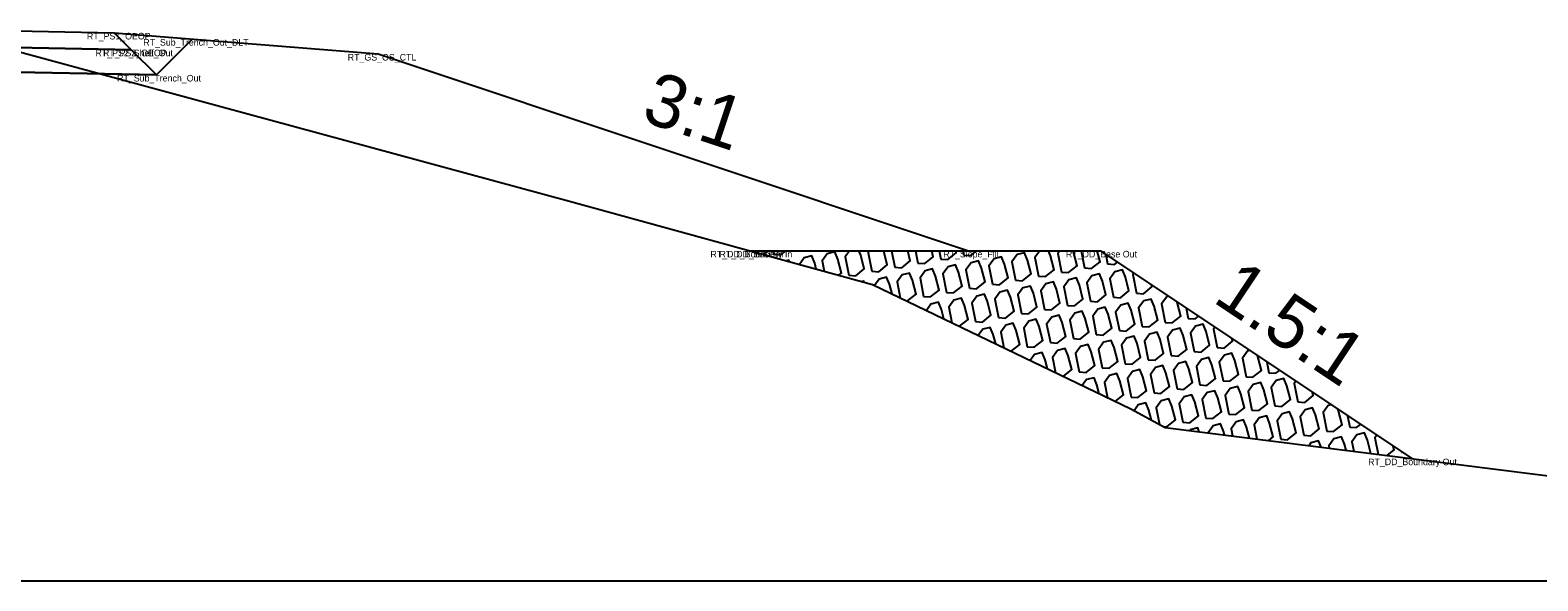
# Model space of a CAD drawing. Extents: x -26 to 203, y -10 to 20020.
# Drawn here: x 111.72 to 134.58, y 18500 to 18508.34 of the extents above; entities that cross this region are included whole.
import ezdxf

# ---------------------------------------------------------------- set-up
doc = ezdxf.new("R2010")
doc.units = 0
for name, color, linetype in [('Default', 7, 'Continuous'), ('Exist Cross Section Cell', 7, 'Continuous'), ('Exist XS Ground Line', 7, 'Continuous'), ('Old_Level_1', 7, 'Continuous'), ('Prop CMT Pvmt Surface Shoulder', 7, 'Continuous'), ('Prop CMT Rip Rap Class II', 7, 'Continuous'), ('Prop CMT Shld Paved Course 1', 7, 'Continuous'), ('Prop CMT Shld Paved Course 2', 7, 'Continuous'), ('Prop CMT Slope Grass', 7, 'Continuous'), ('Prop CMT Subgrade Earthwork', 7, 'Continuous'), ('Prop XS Side Slope Text', 7, 'Continuous')]:
    doc.layers.add(name, color=color, linetype=linetype)

msp = doc.modelspace()

# ---------------------------------------------------------------- linework, layer by layer
at = {"layer": 'Exist Cross Section Cell'}
msp.add_line((100, 18500), (200, 18500), dxfattribs=at)
at = {"layer": 'Exist XS Ground Line'}
for p, q in [((111.141, 18508.127), (119.901, 18505.754)), ((119.901, 18505.754), (124.498, 18504.488)), ((124.498, 18504.488), (128.412, 18502.604)), ((128.412, 18502.604), (128.933, 18502.324)), ((128.933, 18502.324), (135.814, 18501.456))]:
    msp.add_line(p, q, dxfattribs=at)
at = {"layer": 'Old_Level_1'}
for p, q in [((122.993, 18505), (123.003, 18504.949)), ((124.786, 18505), (124.835, 18504.752)), ((125.146, 18505), (125.183, 18504.813)), ((125.507, 18505), (125.532, 18504.875)), ((125.868, 18505), (125.881, 18504.936)), ((126.229, 18505), (126.229, 18504.998)), ((127.661, 18505), (127.712, 18504.74)), ((128.032, 18504.946), (128.061, 18504.801)), ((129.254, 18504.132), (129.285, 18503.977)), ((130.476, 18503.317), (130.508, 18503.154)), ((131.697, 18502.502), (131.732, 18502.33)), ((132.516, 18501.957), (132.518, 18501.949)), ((132.518, 18501.949), (132.529, 18501.948))]:
    msp.add_line(p, q, dxfattribs=at)
for points in [[(122.841, 18504.944), (122.889, 18504.983), (122.885, 18505)], [(123.003, 18504.949), (123.108, 18504.941), (123.182, 18505)], [(123.982, 18504.63), (124.024, 18504.663), (123.969, 18504.874), (123.924, 18504.983), (123.81, 18504.954), (123.733, 18504.848), (123.765, 18504.69)], [(124.148, 18505), (124.082, 18504.909), (124.138, 18504.629)], [(124.138, 18504.629), (124.243, 18504.621), (124.372, 18504.725), (124.318, 18504.935), (124.291, 18505)], [(124.452, 18505), (124.431, 18504.971), (124.486, 18504.691)], [(124.486, 18504.691), (124.591, 18504.683), (124.721, 18504.786), (124.667, 18504.997), (124.665, 18505)], [(124.835, 18504.752), (124.94, 18504.744), (125.07, 18504.848), (125.03, 18505)], [(125.183, 18504.813), (125.289, 18504.806), (125.418, 18504.909), (125.395, 18505)], [(125.532, 18504.875), (125.637, 18504.867), (125.767, 18504.971), (125.759, 18505)], [(125.881, 18504.936), (125.986, 18504.929), (126.075, 18505)], [(126.229, 18504.998), (126.334, 18504.99), (126.347, 18505)], [(127.034, 18505), (126.96, 18504.897), (127.015, 18504.617)], [(127.015, 18504.617), (127.12, 18504.609), (127.25, 18504.712), (127.196, 18504.923), (127.164, 18505)], [(127.338, 18505), (127.308, 18504.958), (127.364, 18504.678)], [(127.364, 18504.678), (127.469, 18504.671), (127.599, 18504.774), (127.544, 18504.984), (127.538, 18505)], [(127.712, 18504.74), (127.818, 18504.732), (127.947, 18504.835), (127.905, 18505)], [(123.237, 18504.835), (123.227, 18504.861), (123.185, 18504.85)], [(123.644, 18504.723), (123.621, 18504.812), (123.576, 18504.922), (123.462, 18504.893), (123.39, 18504.793)], [(126.318, 18504.494), (126.423, 18504.486), (126.553, 18504.589), (126.498, 18504.8), (126.453, 18504.91), (126.339, 18504.88), (126.262, 18504.774), (126.318, 18504.494)], [(128.061, 18504.801), (128.166, 18504.794), (128.209, 18504.828)], [(124.369, 18504.523), (124.362, 18504.541), (124.333, 18504.533)], [(124.793, 18504.346), (124.755, 18504.493), (124.71, 18504.602), (124.597, 18504.573), (124.525, 18504.475)], [(125.01, 18504.242), (125.029, 18504.24), (125.158, 18504.344), (125.104, 18504.554), (125.059, 18504.664), (124.945, 18504.634), (124.868, 18504.528), (124.916, 18504.287)], [(128.459, 18504.661), (128.443, 18504.639), (128.498, 18504.359)], [(125.803, 18503.86), (125.815, 18503.859), (125.945, 18503.962), (125.89, 18504.173), (125.845, 18504.283), (125.731, 18504.253), (125.654, 18504.147), (125.701, 18503.909)], [(126.058, 18503.928), (126.164, 18503.921), (126.293, 18504.024), (126.239, 18504.234), (126.194, 18504.344), (126.08, 18504.315), (126.003, 18504.208), (126.058, 18503.928)], [(126.756, 18504.051), (126.861, 18504.044), (126.99, 18504.147), (126.936, 18504.357), (126.891, 18504.467), (126.777, 18504.438), (126.7, 18504.331), (126.756, 18504.051)], [(128.498, 18504.359), (128.604, 18504.351), (128.733, 18504.454), (128.726, 18504.484)], [(128.986, 18504.31), (128.957, 18504.302), (128.88, 18504.196), (128.936, 18503.916)], [(125.579, 18503.968), (125.541, 18504.111), (125.496, 18504.221), (125.383, 18504.192), (125.313, 18504.096)], [(128.936, 18503.916), (129.041, 18503.908), (129.171, 18504.012), (129.116, 18504.222), (129.116, 18504.224)], [(126.364, 18503.59), (126.328, 18503.73), (126.282, 18503.84), (126.169, 18503.811), (126.101, 18503.717)], [(126.596, 18503.478), (126.601, 18503.478), (126.731, 18503.581), (126.676, 18503.792), (126.631, 18503.902), (126.517, 18503.872), (126.44, 18503.766), (126.487, 18503.531)], [(126.844, 18503.547), (126.95, 18503.54), (127.079, 18503.643), (127.025, 18503.853), (126.98, 18503.963), (126.866, 18503.934), (126.789, 18503.827), (126.844, 18503.547)], [(127.193, 18503.609), (127.298, 18503.601), (127.428, 18503.704), (127.373, 18503.915), (127.328, 18504.024), (127.214, 18503.995), (127.137, 18503.889), (127.193, 18503.609)], [(129.285, 18503.977), (129.39, 18503.97), (129.438, 18504.009)], [(129.687, 18503.843), (129.666, 18503.815), (129.722, 18503.535)], [(127.979, 18503.227), (128.084, 18503.22), (128.214, 18503.323), (128.159, 18503.534), (128.114, 18503.643), (128.001, 18503.614), (127.923, 18503.507), (127.979, 18503.227)], [(128.328, 18503.289), (128.433, 18503.281), (128.562, 18503.385), (128.508, 18503.595), (128.463, 18503.705), (128.349, 18503.675), (128.272, 18503.569), (128.328, 18503.289)], [(129.722, 18503.535), (129.827, 18503.527), (129.957, 18503.63), (129.947, 18503.67)], [(127.149, 18503.212), (127.114, 18503.349), (127.068, 18503.459), (126.955, 18503.43), (126.888, 18503.338)], [(127.388, 18503.097), (127.517, 18503.2), (127.462, 18503.411), (127.417, 18503.52), (127.303, 18503.491), (127.226, 18503.385), (127.272, 18503.153)], [(127.63, 18503.166), (127.736, 18503.158), (127.865, 18503.262), (127.811, 18503.472), (127.766, 18503.582), (127.652, 18503.552), (127.575, 18503.446), (127.63, 18503.166)], [(129.462, 18502.969), (129.568, 18502.962), (129.697, 18503.065), (129.643, 18503.275), (129.598, 18503.385), (129.484, 18503.356), (129.407, 18503.249), (129.462, 18502.969)], [(130.219, 18503.488), (130.181, 18503.479), (130.104, 18503.372), (130.16, 18503.092)], [(130.16, 18503.092), (130.265, 18503.085), (130.394, 18503.188), (130.34, 18503.398), (130.335, 18503.411)], [(128.176, 18502.718), (128.303, 18502.819), (128.248, 18503.03), (128.203, 18503.139), (128.089, 18503.11), (128.012, 18503.003), (128.058, 18502.775)], [(129.114, 18502.908), (129.219, 18502.9), (129.349, 18503.003), (129.294, 18503.214), (129.249, 18503.324), (129.135, 18503.294), (129.058, 18503.188), (129.114, 18502.908)], [(130.508, 18503.154), (130.613, 18503.146), (130.667, 18503.189)], [(127.934, 18502.834), (127.9, 18502.968), (127.855, 18503.078), (127.741, 18503.048), (127.676, 18502.959)], [(130.248, 18502.588), (130.354, 18502.581), (130.483, 18502.684), (130.429, 18502.894), (130.384, 18503.004), (130.27, 18502.975), (130.193, 18502.868), (130.248, 18502.588)], [(130.597, 18502.65), (130.702, 18502.642), (130.832, 18502.745), (130.777, 18502.956), (130.732, 18503.065), (130.618, 18503.036), (130.541, 18502.93), (130.597, 18502.65)], [(130.914, 18503.025), (130.89, 18502.991), (130.946, 18502.711)], [(128.725, 18502.436), (128.686, 18502.587), (128.641, 18502.697), (128.527, 18502.667), (128.462, 18502.578)], [(128.907, 18502.338), (128.959, 18502.335), (129.089, 18502.438), (129.034, 18502.648), (128.989, 18502.758), (128.875, 18502.729), (128.798, 18502.622), (128.849, 18502.37)], [(130.946, 18502.711), (131.051, 18502.703), (131.18, 18502.807), (131.168, 18502.856)], [(130.505, 18502.126), (130.572, 18502.18), (130.518, 18502.39), (130.473, 18502.5), (130.359, 18502.471), (130.282, 18502.364), (130.324, 18502.149)], [(131.451, 18502.667), (131.405, 18502.655), (131.327, 18502.548), (131.383, 18502.268)], [(131.383, 18502.268), (131.488, 18502.261), (131.618, 18502.364), (131.563, 18502.575), (131.554, 18502.598)], [(129.45, 18502.259), (129.427, 18502.316), (129.313, 18502.286), (129.307, 18502.277)], [(129.835, 18502.211), (129.82, 18502.267), (129.775, 18502.377), (129.662, 18502.348), (129.585, 18502.242)], [(130.212, 18502.163), (130.169, 18502.329), (130.124, 18502.438), (130.01, 18502.409), (129.933, 18502.303), (129.954, 18502.195)], [(131.732, 18502.33), (131.837, 18502.322), (131.896, 18502.37)], [(132.053, 18501.931), (132.001, 18502.132), (131.956, 18502.242), (131.842, 18502.212), (131.765, 18502.106), (131.793, 18501.963)], [(131.297, 18502.026), (131.259, 18502.119), (131.145, 18502.089), (131.116, 18502.049)], [(131.676, 18501.978), (131.652, 18502.071), (131.607, 18502.18), (131.493, 18502.151), (131.416, 18502.044), (131.423, 18502.01)], [(132.142, 18502.206), (132.114, 18502.167), (132.163, 18501.917)], [(132.299, 18501.9), (132.404, 18501.983), (132.389, 18502.042)]]:
    msp.add_lwpolyline(points, dxfattribs=at)
for points in [[(126.667, 18504.555), (126.772, 18504.548), (126.901, 18504.651), (126.847, 18504.861), (126.802, 18504.971), (126.688, 18504.942), (126.611, 18504.835)], [(125.621, 18504.371), (125.726, 18504.363), (125.856, 18504.466), (125.801, 18504.677), (125.756, 18504.787), (125.642, 18504.757), (125.565, 18504.651)], [(125.969, 18504.432), (126.075, 18504.425), (126.204, 18504.528), (126.15, 18504.739), (126.105, 18504.848), (125.991, 18504.819), (125.914, 18504.712)], [(125.272, 18504.309), (125.378, 18504.302), (125.507, 18504.405), (125.453, 18504.616), (125.407, 18504.725), (125.294, 18504.696), (125.217, 18504.589)], [(127.104, 18504.113), (127.209, 18504.105), (127.339, 18504.208), (127.284, 18504.419), (127.239, 18504.529), (127.126, 18504.499), (127.049, 18504.393)], [(127.453, 18504.174), (127.558, 18504.167), (127.688, 18504.27), (127.633, 18504.48), (127.588, 18504.59), (127.474, 18504.561), (127.397, 18504.454)], [(127.801, 18504.236), (127.907, 18504.228), (128.036, 18504.331), (127.982, 18504.542), (127.937, 18504.651), (127.823, 18504.622), (127.746, 18504.516)], [(128.15, 18504.297), (128.255, 18504.289), (128.385, 18504.393), (128.33, 18504.603), (128.285, 18504.713), (128.171, 18504.684), (128.094, 18504.577)], [(126.407, 18503.99), (126.512, 18503.982), (126.642, 18504.085), (126.587, 18504.296), (126.542, 18504.406), (126.428, 18504.376), (126.351, 18504.27)], [(127.542, 18503.67), (127.647, 18503.662), (127.776, 18503.766), (127.722, 18503.976), (127.677, 18504.086), (127.563, 18504.057), (127.486, 18503.95)], [(127.89, 18503.732), (127.995, 18503.724), (128.125, 18503.827), (128.071, 18504.038), (128.025, 18504.147), (127.912, 18504.118), (127.835, 18504.012)], [(128.239, 18503.793), (128.344, 18503.785), (128.474, 18503.889), (128.419, 18504.099), (128.374, 18504.209), (128.26, 18504.179), (128.183, 18504.073)], [(128.587, 18503.854), (128.693, 18503.847), (128.822, 18503.95), (128.768, 18504.161), (128.723, 18504.27), (128.609, 18504.241), (128.532, 18504.134)], [(129.025, 18503.412), (129.13, 18503.404), (129.26, 18503.507), (129.205, 18503.718), (129.16, 18503.828), (129.046, 18503.798), (128.969, 18503.692)], [(129.373, 18503.473), (129.479, 18503.466), (129.608, 18503.569), (129.554, 18503.779), (129.509, 18503.889), (129.395, 18503.86), (129.318, 18503.753)], [(128.676, 18503.35), (128.782, 18503.343), (128.911, 18503.446), (128.857, 18503.657), (128.811, 18503.766), (128.698, 18503.737), (128.621, 18503.63)], [(129.811, 18503.031), (129.916, 18503.023), (130.046, 18503.126), (129.991, 18503.337), (129.946, 18503.447), (129.832, 18503.417), (129.755, 18503.311)], [(128.417, 18502.785), (128.522, 18502.777), (128.651, 18502.88), (128.597, 18503.091), (128.552, 18503.201), (128.438, 18503.171), (128.361, 18503.065)], [(128.765, 18502.846), (128.87, 18502.839), (129, 18502.942), (128.945, 18503.152), (128.9, 18503.262), (128.787, 18503.233), (128.71, 18503.126)], [(129.9, 18502.527), (130.005, 18502.519), (130.135, 18502.622), (130.08, 18502.833), (130.035, 18502.943), (129.921, 18502.913), (129.844, 18502.807)], [(129.203, 18502.404), (129.308, 18502.396), (129.437, 18502.499), (129.383, 18502.71), (129.338, 18502.82), (129.224, 18502.79), (129.147, 18502.684)], [(129.551, 18502.465), (129.656, 18502.458), (129.786, 18502.561), (129.732, 18502.771), (129.686, 18502.881), (129.573, 18502.852), (129.496, 18502.745)], [(130.686, 18502.146), (130.791, 18502.138), (130.921, 18502.241), (130.866, 18502.452), (130.821, 18502.561), (130.707, 18502.532), (130.63, 18502.426)], [(131.034, 18502.207), (131.14, 18502.199), (131.269, 18502.303), (131.215, 18502.513), (131.17, 18502.623), (131.056, 18502.593), (130.979, 18502.487)]]:
    msp.add_lwpolyline(points, close=True, dxfattribs=at)
at = {"layer": 'Prop CMT Pvmt Surface Shoulder'}
msp.add_lwpolyline([(111, 18508.343), (113, 18508.303)], dxfattribs=at)
at = {"layer": 'Prop CMT Rip Rap Class II'}
for points in [[(122.639, 18505), (122.639, 18505)], [(122.639, 18505), (127.951, 18505), (132.672, 18501.852)]]:
    msp.add_lwpolyline(points, dxfattribs=at)
at = {"layer": 'Prop CMT Shld Paved Course 1'}
for points in [[(111, 18508.343), (113, 18508.303), (113.255, 18508.048)], [(113.255, 18508.048), (111, 18508.093)]]:
    msp.add_lwpolyline(points, dxfattribs=at)
at = {"layer": 'Prop CMT Shld Paved Course 2'}
for points in [[(111, 18508.093), (113.255, 18508.048)], [(113.255, 18508.048), (113.255, 18508.048)], [(113.255, 18508.048), (113.638, 18507.666)], [(113.638, 18507.666), (111, 18507.718)]]:
    msp.add_lwpolyline(points, dxfattribs=at)
at = {"layer": 'Prop CMT Slope Grass'}
msp.add_lwpolyline([(113, 18508.303), (117, 18507.983), (125.951, 18505)], dxfattribs=at)
at = {"layer": 'Prop CMT Subgrade Earthwork'}
for points in [[(113.638, 18507.666), (114.181, 18508.209)], [(111, 18507.718), (113.638, 18507.666)]]:
    msp.add_lwpolyline(points, dxfattribs=at)

# ---------------------------------------------------------------- texts
at = {"layer": 'Default'}
for s, p in [('RT_PS1_OEOP', (112.585, 18508.203)), ('RT_Sub_Trench_Out_DLT', (113.44, 18508.109)), ('RT_PS2_Shelf_Out', (112.715, 18507.948)), ('RT_PS2_OEOP', (112.828, 18507.948)), ('RT_GS_OS_CTL', (116.54, 18507.883)), ('RT_Sub_Trench_Out', (113.043, 18507.566)), ('RT_DD_Boundary In', (122.039, 18504.9)), ('RT_DD_Base In', (122.177, 18504.9)), ('RT_Slope_Fill', (125.569, 18504.9)), ('RT_DD_Base Out', (127.429, 18504.9)), ('RT_DD_Boundary Out', (132.011, 18501.752))]:
    msp.add_text(s, height=0.1, dxfattribs=at).set_placement(p)
at = {"layer": 'Prop XS Side Slope Text'}
for s, rotation, p in [('3:1', 341.5668, (120.969, 18506.977)), ('1.5:1', 326.3086, (129.636, 18504.238))]:
    msp.add_text(s, height=0.8, rotation=rotation, dxfattribs=at).set_placement(p)

doc.saveas('drawing.dxf')
